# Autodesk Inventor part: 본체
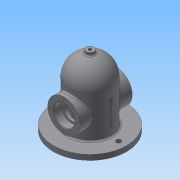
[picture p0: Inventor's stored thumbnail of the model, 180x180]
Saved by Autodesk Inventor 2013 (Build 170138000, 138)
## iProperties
Created: 2019-11
Part Number: 본체
Material: 일반
Document SubType Name: Modeling
Designer: Administrator
Density: 1 g/cm^3
Author: Administrator
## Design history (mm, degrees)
sketch "스케치1"
  geometry: C1 r 70 at (0, 0); 1 further point
  constraints: 1 centre point, 1 coincident
  dimensions: "d0" = 140 diameter of C1
extrude "돌출1" new body sketch "스케치1" distance "d1" = 10; taper "d2" = 0 deg
sketch "스케치2"
  geometry: C1 r 70 at (0, 0) reference; C2 r 40 at (0, 0)
  constraints: 1 centre point, 1 coincident
  dimensions: "d3" = 80 diameter of C2
extrude "돌출2" join sketch "스케치2" distance "d4" = 120; taper "d5" = 0 deg
sketch "스케치3"
  geometry: L1 (-70, 0)-(70, 0) reference; L2 (-40, 10)-(40, 10) reference; C1 r 31 at (0, 50); 1 further point
  constraints: 1 centre point, 1 vertical alignment
  dimensions: "d7" = 62 diameter of C1; "d8" = 40 distance from line of L2 C1.centre
extrude "돌출3" join sketch "스케치3" stored distance "d9" = 100; taper "d10" = 0 deg
sketch "스케치4"
  geometry: C1 r 31 at (0, 0) reference; C2 r 20 at (0, 0); 1 further point
  constraints: 1 centre point, 1 coincident
  dimensions: "d11" = 40 diameter of C2
extrude "돌출4" cut sketch "스케치4" distance "d12" = 15; taper "d13" = 0 deg
sketch "스케치5"
  geometry: C1 r 20 at (0, 0) reference; C2 r 16.5 at (0, 0); 1 further point
  constraints: 1 centre point, 1 coincident
  dimensions: "d14" = 33 diameter of C2
extrude "돌출5" cut sketch "스케치5" stored distance "d15" = 15; taper "d16" = 0 deg
fillet "모깎기1" dims "d17" = 40
sketch "스케치7"
  geometry: L1 (40, 90)-(-40, 90) reference; L2 (-70, 0)-(70, 0) reference; 1 further point
  node "투영된 루프1"
sketch "스케치8"
  geometry: L1 (0, 0)-(30, 0); L2 (30, 0)-(30, 90); L3 (0, 120)-(0, 120); L4 (0, 120)-(0, 0); A1 r 30 centre (0, 90) between (30, 90) and (0, 120); 1 further point
  constraints: 8 end point, 2 parallel, 2 point on circle, 2 point on line, 2 tangent, 1 centre point, 1 horizontal, 1 perpendicular
  dimensions: "d18" = 30 distance of L3.end point (30, 120); "d19" = 120 distance of point (30, 120) L1.end; "d20" = 30 radius of A1
revolve "회전1" sketch "스케치8" stored, may be unused: angle "d21" = 90 deg
sketch "스케치9"
  geometry: C1 r 20 at (0, 0) reference; C2 r 20 at (0, 0) reference; C3 r 31 at (0, 0) reference; 2 further points
  constraints: 1 vertical alignment
  dimensions: "d22" = 26 distance of point (0, 26) C1.centre
hole "구멍1" sketch "스케치9" at (0, 26) diameter "d23" = 3.242; stored, may be unused: countersink angle "d27" = 90 deg, drill point angle "d29" = 118 deg; dims "d24" = 8, "d25" = 4, "d26" = 2, "d28" = 10
sketch "스케치10"
  geometry: C1 r 30 at (0, 0) reference; C2 r 70 at (0, 0) reference; A1 r 55 centre (0, 0) between (55, 0) and (-55, 0)
  constraints: 2 horizontal alignment, 2 point on circle, 1 centre point, 1 coincident
  dimensions: "d33" = 110 diameter of A1
hole "구멍2" sketch "스케치10" at (55, 0), (-55, 0) diameter "d34" = 9; stored, may be unused: countersink angle "d38" = 90 deg, drill point angle "d40" = 118 deg; dims "d35" = 8, "d36" = 4, "d37" = 2, "d39" = 10
node "작업 평면1"
sketch "스케치11"
  geometry: C1 r 40 at (0, 0) reference; C2 r 7.5 at (0, 0); 1 further point
  constraints: 1 centre point, 1 coincident
  dimensions: "d42" = 15 diameter of C2
extrude "돌출6" join sketch "스케치11" stored distance "d43" = 120; taper "d44" = 0 deg
sketch "스케치12"
  geometry: C1 r 7.5 at (0, 0) reference; 1 further point
  constraints: 1 coincident
hole "구멍3" sketch "스케치12" at (0, 0) diameter "d45" = 5.188; stored, may be unused: countersink angle "d49" = 90 deg, drill point angle "d51" = 118 deg; dims "d46" = 19, "d47" = 4, "d48" = 2, "d50" = 20
node "작업 평면2"
sketch "스케치13"
  geometry: L1 (-70, 0)-(70, 0) reference; 2 further points
  constraints: 1 vertical alignment, 1 other
  dimensions: "d53" = 50 distance from line of L1 point (0, 50)
feature "엠보싱1" sketch "스케치13" dims "d1" = 10, "d2" = 0, "d54" = 0.5, "d55" = 0
fillet "모깎기2" dims "d56" = 3
chamfer "모따기2" distance "d60" = 1; stored, may be unused: second distance "d61" = 2, angle "d62" = 45 deg
fillet "모깎기3" dims "d63" = 0.3
node "솔리드1"
mirror "대칭1"
pattern_circular "원형 패턴1" dims angle "d31" = 360 deg
mirror "대칭2"
node "투영된 루프2"
node "투영된 루프3"
other parameters: "d41" = 135
